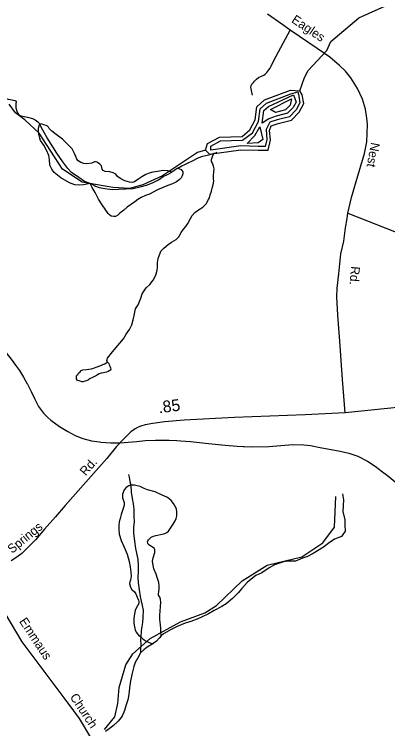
# Model space of a CAD drawing. Extents: x 2206922 to 2357709, y 510027 to 673830.
# Drawn here: x 2302635 to 2306591, y 537168 to 544730 of the extents above; entities that cross this region are included whole.
import ezdxf

# ---------------------------------------------------------------- set-up
doc = ezdxf.new("R2010")
doc.units = 0
for name, color, linetype in [('Exist Hydrographic Buffer Line', 7, 'Continuous'), ('Exist Hydrographic Creek Single Shore', 7, 'Continuous'), ('Exist Hydrographic Lake Shore', 7, 'Continuous'), ('Exist Hydrographic Misc Water Feature', 7, 'Continuous'), ('Exist Road Non-System Type 51', 7, 'Continuous'), ('Exist Road Secondary Mileage Hundredths English Label', 7, 'Continuous'), ('Exist Road Secondary Type 51 Attributed', 7, 'Continuous'), ('Exist Road Secondary Type 51 Label', 7, 'Continuous')]:
    doc.layers.add(name, color=color, linetype=linetype)

msp = doc.modelspace()

# ---------------------------------------------------------------- linework, layer by layer
at = {"layer": 'Exist Hydrographic Buffer Line'}
for points in [[(2305636.8, 543908.3), (2305647.3, 543862.6), (2305661.2, 543792.4), (2305621.8, 543719.4), (2305550.5, 543646.2), (2305420.5, 543613.7), (2305343, 543586.7), (2305301.5, 543511.9), (2305308.7, 543403.3), (2305292.9, 543331.4), (2305217.7, 543330.6), (2305034.6, 543336.3), (2304715.3, 543292.4), (2304715.9, 543333.3), (2304818.2, 543388.8), (2305050.8, 543398.2), (2305157, 543476.4), (2305223.4, 543595.6), (2305241.2, 543730), (2305307.5, 543790.2), (2305565.6, 543887.2), (2305636.8, 543908.3)], [(2305258.9, 543576.9), (2305279.4, 543710.6), (2305328.8, 543755.5), (2305591.1, 543878.9), (2305619.2, 543798.8), (2305589.2, 543743.3), (2305529.8, 543682.2), (2305410.6, 543652.5), (2305329.6, 543624.4), (2305258.9, 543576.9)], [(2305401.2, 543691.3), (2305349.9, 543720.7), (2305571.4, 543833.4), (2305556.4, 543767.2), (2305509, 543718.3), (2305401.2, 543691.3)], [(2305101.8, 543361.9), (2305182.8, 543445.8), (2305237.6, 543540), (2305268.3, 543405.6), (2305217.9, 543370.6), (2305101.8, 543361.9)]]:
    msp.add_lwpolyline(points, dxfattribs=at)
at = {"layer": 'Exist Hydrographic Creek Single Shore'}
for points in [[(2305660.2, 543918.8), (2305708.2, 544061.9), (2305749.2, 544135.7), (2305947.2, 544347.2), (2305987.2, 544440.7), (2306284.1, 544692.2), (2306591.3, 544829.3), (2306766.2, 544865.8), (2307040.2, 544860.5), (2307516.3, 544755), (2307941.2, 544752.4), (2308166.3, 544778)], [(2304659.3, 543291.1), (2304576.3, 543268.1), (2304204.3, 543020.1), (2303996.2, 542926.4), (2303855.1, 542884.6), (2303680.2, 542897.2), (2303355.2, 542953.1), (2303145.2, 543092.2), (2302900.2, 543472.9), (2302748.2, 543614.3), (2302647.1, 543685.8), (2302580.1, 543778.2)]]:
    msp.add_lwpolyline(points, dxfattribs=at)
at = {"layer": 'Exist Hydrographic Lake Shore'}
for points in [[(2304659.3, 543291.1), (2304683.3, 543361), (2304807.2, 543428.4), (2305049.1, 543438.1), (2305131.1, 543507.1), (2305188.1, 543614.3), (2305203.3, 543749.5), (2305286.2, 543825), (2305560.3, 543927.9), (2305660.2, 543918.8)], [(2305339.3, 543499.1), (2305356.3, 543548.9), (2305430.3, 543574.9), (2305571.2, 543610.1), (2305654.2, 543695.5), (2305703.2, 543786), (2305685.2, 543877.2), (2305660.2, 543918.8)], [(2304659.3, 543291.1), (2304701.1, 543250.1), (2305033.1, 543296.4), (2305217.3, 543290.6), (2305325.3, 543291.7), (2305349.3, 543401), (2305339.3, 543499.1)]]:
    msp.add_lwpolyline(points, dxfattribs=at)
at = {"layer": 'Exist Hydrographic Misc Water Feature'}
msp.add_line((2302772, 540819.9), (2302775.1, 540814.4), dxfattribs=at)
for points in [[(2302511.4, 543852.5), (2302531.9, 543844.9), (2302547.9, 543838.9), (2302571.7, 543831.2), (2302613.7, 543823.7), (2302641.6, 543817.9), (2302656, 543812.1), (2302656, 543804.4), (2302652.3, 543784.2), (2302652.5, 543760.3), (2302652.5, 543740.4), (2302660.9, 543704.3), (2302673.2, 543678.5), (2302685.5, 543662.4), (2302709.3, 543654.8), (2302739.4, 543649.1), (2302775.5, 543641.6), (2302827.6, 543628.1), (2302856.1, 543614.5), (2302884.4, 543590.7), (2302906.3, 543569.2)], [(2303439, 542939.1), (2303368.9, 542924.6), (2303325.2, 542920.1), (2303277.3, 542925.4), (2303220.9, 542946.8), (2303128.6, 542999.7), (2303057.9, 543054.9), (2303033.7, 543090.6), (2303010.7, 543134.6), (2303006.4, 543192.4), (2302999.6, 543236.4), (2302977.5, 543292.1), (2302948.8, 543343.8), (2302912.1, 543395.1), (2302903.9, 543419.1), (2302897.9, 543447.2), (2302893, 543484.8), (2302893, 543505.1), (2302893, 543522.9), (2302898.1, 543550.9), (2302906.3, 543569.2)], [(2304305, 543060.6), (2304263.1, 543072.1), (2304211.1, 543075.5), (2304151, 543066.8), (2304103, 543060.1), (2304065.3, 543050), (2304029.2, 543035.6), (2303985.5, 543010.9), (2303953.9, 542986.9), (2303908.4, 542956), (2303882.4, 542949.8), (2303854.7, 542951.6), (2303806.1, 542967), (2303762.2, 542986.6), (2303729.8, 543014.2), (2303709.7, 543036.3), (2303683.3, 543051.6), (2303645.5, 543061.3), (2303599.2, 543067.1), (2303585.2, 543072.8), (2303575.4, 543076.8), (2303565.4, 543090.4), (2303558.6, 543124.3), (2303542.4, 543144.2), (2303526.4, 543155.9), (2303510.4, 543164), (2303496.5, 543169.7), (2303484.2, 543167.5), (2303456.7, 543155), (2303404.6, 543148.7), (2303372.4, 543152.3), (2303338.4, 543159.8), (2303312.5, 543177.5), (2303298.4, 543197.5), (2303286.1, 543223.3), (2303271.7, 543257.1), (2303246.9, 543307), (2303200.6, 543350.1), (2303146.2, 543409.8), (2303063.6, 543466.9), (2303033.2, 543492.5), (2303004.7, 543522.3), (2302996.7, 543536.1), (2302988.3, 543545.9), (2302972.1, 543554), (2302948.4, 543561.6), (2302928.5, 543567.4), (2302906.3, 543569.2)], [(2303439, 542939.1), (2303380.4, 542960.5), (2303318.1, 543002), (2303241.4, 543056.9), (2303201.2, 543096.6), (2303148.3, 543169.8), (2303085.9, 543259.1), (2303043.1, 543328.8), (2302982, 543422), (2302953.1, 543477.8), (2302924.8, 543529.1), (2302906.3, 543569.2)], [(2303623.2, 541048.1), (2303616.8, 541066.1), (2303623, 541090.3), (2303634.7, 541106.4), (2303660.3, 541138.6), (2303693.9, 541179), (2303790.3, 541293.8), (2303819.6, 541344.2), (2303855.1, 541394.4), (2303878.9, 541444.7), (2303894.3, 541494.7), (2303905.7, 541542.9), (2303918.9, 541611), (2303948.4, 541653.2), (2303975.9, 541723.7), (2303989.4, 541769.9), (2304032.5, 541834), (2304070, 541870.5), (2304105.5, 541915), (2304135, 541967.4), (2304148.5, 542021.3), (2304152, 542051.6), (2304153.4, 542101.3), (2304159.2, 542143.4), (2304178.7, 542201.7), (2304188.3, 542221.7), (2304217.8, 542255.8), (2304263.4, 542292.3), (2304300.9, 542318.7), (2304350.7, 542347.3), (2304378.6, 542373.5), (2304402, 542419.9), (2304427.2, 542454.2), (2304453, 542484.4), (2304474.8, 542514.8), (2304500.4, 542566.8), (2304518, 542601.1), (2304547.6, 542633.1), (2304585.1, 542659.9), (2304633.3, 542688.4), (2304666.5, 542722.7), (2304693.8, 542768.9), (2304701.8, 542788.8), (2304711.4, 542818.9), (2304722.9, 542856.9), (2304734.4, 542903.1), (2304740.3, 542925.3), (2304747.9, 542963.5), (2304745.2, 542991.5), (2304745.4, 543025.1), (2304748.5, 543059.1), (2304750.8, 543095.3), (2304746.5, 543123), (2304736, 543155), (2304723.7, 543171.1), (2304723.7, 543193), (2304729.4, 543214.9), (2304739.1, 543236.9), (2304750.8, 543261.1)], [(2304366.5, 543101.2), (2304410.2, 543125.5), (2304441.7, 543141.8), (2304478, 543158.2), (2304523.6, 543178.9), (2304583, 543209.3), (2304632.9, 543229.8), (2304711, 543246.8), (2304750.8, 543261.1)], [(2304750.8, 543261.1), (2304768.4, 543265.3), (2304784.2, 543271.4)], [(2304366.5, 543101.2), (2304384.7, 543095.2), (2304400.9, 543085.5), (2304410.8, 543075.5), (2304421, 543063.8), (2304421.2, 543053.6), (2304421.2, 543041.8), (2304413.2, 543021.5), (2304402, 542999.3), (2304381.7, 542977.3), (2304351.9, 542955), (2304310.3, 542934.4), (2304262.5, 542918.1), (2304151, 542870.9), (2304067.9, 542826.2), (2304025.9, 542811.4), (2303980, 542791.2), (2303942.2, 542768.9), (2303912.7, 542746.6), (2303830.9, 542689.5), (2303793.6, 542657), (2303753.8, 542624.9), (2303732.3, 542604.6), (2303708.7, 542590.4), (2303684.3, 542590), (2303662.6, 542591.6), (2303642.3, 542607.6), (2303627.9, 542621.5), (2303565.4, 542712.5), (2303528.4, 542774), (2303491.9, 542843.6), (2303459.1, 542897.5), (2303439, 542939.1)], [(2304366.5, 543101.2), (2304338.4, 543082.7), (2304305, 543060.6)], [(2303439, 542939.1), (2303462.8, 542927.4), (2303495.2, 542911.6), (2303535, 542898.3), (2303593.4, 542884.6), (2303673.2, 542875.9), (2303739.2, 542878.5), (2303815.3, 542881.2), (2303895.1, 542886.3), (2303968.9, 542902.7), (2304036.6, 542921.7), (2304100.5, 542946.1), (2304163.9, 542978.8), (2304213.5, 543011.5), (2304259.3, 543035.8), (2304305, 543060.6)], [(2302314.1, 541436.1), (2302322.3, 541426.9), (2302393.3, 541341.4), (2302613.1, 541064.3), (2302649.4, 541017.1), (2302690.2, 540958.6)], [(2302314.1, 541436.1), (2302322.3, 541426.9), (2302393.3, 541341.4), (2302613.1, 541064.3), (2302649.4, 541017.1), (2302690.2, 540958.6)], [(2303623.2, 541048.1), (2303635.5, 541034.5), (2303641.6, 541020.6), (2303649.8, 540998.7), (2303653.7, 540986.7), (2303656.2, 540972.6), (2303653.9, 540964.8), (2303648.2, 540958.4), (2303628.1, 540950.4), (2303610.3, 540942.2), (2303592.6, 540938), (2303580.7, 540935.7), (2303556.5, 540931.6), (2303532.8, 540923.4), (2303516.6, 540913.3), (2303494.6, 540900.8), (2303485, 540897), (2303455, 540880.4), (2303439, 540874.3), (2303419.4, 540860.2), (2303401.3, 540852), (2303383.3, 540845.8), (2303363.6, 540841.5), (2303349.4, 540841.5), (2303333.4, 540845.2), (2303321.3, 540849), (2303305.4, 540855.1), (2303293.3, 540870.7), (2303293.5, 540884.8), (2303294.9, 540898.8), (2303298.6, 540908.8), (2303306.8, 540918.9), (2303316.4, 540930.9), (2303332.2, 540947.1), (2303344.1, 540959.1), (2303359.9, 540965.3), (2303400.1, 540971.8), (2303424.1, 540972.3), (2303452, 540976.6), (2303483.7, 540986.8), (2303503.8, 540995.1), (2303551.6, 541013.5), (2303573.1, 541023.6), (2303593.2, 541031.9), (2303609, 541040.1), (2303623.2, 541048.1)], [(2302690.2, 540958.6), (2302733.3, 540889.4), (2302772, 540819.9)], [(2302690.2, 540958.6), (2302733.3, 540889.4), (2302772, 540819.9)], [(2302775.1, 540814.4), (2302813.2, 540738.7), (2302851.2, 540657.2)], [(2302775.1, 540814.4), (2302813.2, 540738.7), (2302851.2, 540657.2)], [(2302851.2, 540657.2), (2302891.1, 540580.3), (2302944.5, 540506.7), (2302990.6, 540463.2)], [(2302851.2, 540657.2), (2302891.1, 540580.3), (2302944.5, 540506.7), (2302990.6, 540463.2)], [(2302990.6, 540463.2), (2303021.1, 540434.3), (2303115.3, 540366.4), (2303201.2, 540312.9), (2303279.5, 540273.2)], [(2302990.6, 540463.2), (2303021.1, 540434.3), (2303115.3, 540366.4), (2303201.2, 540312.9), (2303279.5, 540273.2)], [(2303279.5, 540273.2), (2303361.1, 540240.4), (2303451.1, 540217), (2303538.9, 540203.6)], [(2303279.5, 540273.2), (2303361.1, 540240.4), (2303451.1, 540217), (2303538.9, 540203.6)], [(2303756.3, 540194.4), (2303842.2, 540200.5), (2303934, 540209.7)], [(2303756.3, 540194.4), (2303842.2, 540200.5), (2303934, 540209.7)], [(2303934, 540209.7), (2304020.2, 540218.3), (2304132.3, 540222.5), (2304203.5, 540221.9)], [(2303934, 540209.7), (2304020.2, 540218.3), (2304132.3, 540222.5), (2304203.5, 540221.9)], [(2304203.5, 540221.9), (2304275.2, 540221.4), (2304356.9, 540218.2)], [(2304203.5, 540221.9), (2304275.2, 540221.4), (2304356.9, 540218.2)], [(2304356.9, 540218.2), (2304394, 540216.7), (2304502.4, 540208.9), (2304692.7, 540188.7)], [(2304356.9, 540218.2), (2304394, 540216.7), (2304502.4, 540208.9), (2304692.7, 540188.7)], [(2303538.9, 540203.6), (2303551.2, 540201.7), (2303656.2, 540194.4), (2303756.3, 540194.4)], [(2304692.7, 540188.7), (2304868.3, 540170.2), (2304997.2, 540158.6), (2305058.5, 540155.3)], [(2304692.7, 540188.7), (2304868.3, 540170.2), (2304997.2, 540158.6), (2305058.5, 540155.3)], [(2305058.5, 540155.3), (2305070.2, 540154.7), (2305162.3, 540152.2)], [(2305058.5, 540155.3), (2305070.2, 540154.7), (2305162.3, 540152.2)], [(2305162.3, 540152.2), (2305331.3, 540155.7), (2305585.3, 540176.2), (2305702.2, 540174), (2305771.3, 540165.2), (2305873.4, 540145.4)], [(2305162.3, 540152.2), (2305331.3, 540155.7), (2305585.3, 540176.2), (2305702.2, 540174), (2305771.3, 540165.2), (2305873.4, 540145.4)], [(2305873.4, 540145.4), (2306086.3, 540104.2), (2306179.6, 540083.4), (2306274.5, 540051.3), (2306375.2, 539999.9)], [(2305873.4, 540145.4), (2306086.3, 540104.2), (2306179.6, 540083.4), (2306274.5, 540051.3), (2306375.2, 539999.9)], [(2306375.2, 539999.9), (2306436.3, 539961.6), (2306472, 539935.6)], [(2306375.2, 539999.9), (2306436.3, 539961.6), (2306472, 539935.6)], [(2306472, 539935.6), (2306488.4, 539923.8), (2306535.3, 539888.7), (2306587.2, 539846.6)], [(2306472, 539935.6), (2306488.4, 539923.8), (2306535.3, 539888.7), (2306587.2, 539846.6)], [(2303845.9, 539857.3), (2303852.2, 539831.3), (2303860.6, 539785.5), (2303869, 539745.6)], [(2306587.2, 539846.6), (2306825.3, 539653.9), (2306889.3, 539605.1), (2306954.3, 539561.6), (2307014.3, 539529.6)], [(2306587.2, 539846.6), (2306825.3, 539653.9), (2306889.3, 539605.1), (2306954.3, 539561.6), (2307014.3, 539529.6)], [(2303869, 539745.6), (2303849.1, 539737.4), (2303821.5, 539721.1), (2303799.7, 539694.9), (2303782.3, 539650.7), (2303782.5, 539610.7), (2303797.1, 539562.9), (2303797.5, 539535), (2303787.6, 539500.8), (2303768.6, 539434.7), (2303756.9, 539394.6), (2303747.2, 539356.5), (2303741.7, 539316.5), (2303742.3, 539280.5), (2303746.6, 539228.6), (2303767.5, 539160.8), (2303800.1, 539089.2), (2303829.1, 539015.6), (2303851.8, 538937.9), (2303862.5, 538882.1), (2303870.9, 538824.2), (2303871.5, 538784.1), (2303866, 538742.2), (2303860.2, 538722.1), (2303856.3, 538704.1), (2303864.7, 538666.1), (2303880.9, 538642.3), (2303907.2, 538616.7), (2303921.5, 538594.8), (2303937.7, 538561), (2303952.3, 538527.2), (2303954.1, 538513.2), (2303952.5, 538495.2), (2303938.8, 538467.1), (2303927.1, 538445), (2303915.2, 538418.8), (2303907.8, 538382.8), (2303902.3, 538334.8), (2303900.8, 538286.8), (2303909.2, 538244.9), (2303915.4, 538215), (2303927.7, 538189.1), (2303952.3, 538159.4), (2303974.2, 538141.7)], [(2304189.9, 538152), (2304187.7, 538191.9), (2304187.3, 538229.9), (2304184.8, 538267.8), (2304176.2, 538323.7), (2304175.8, 538365.7), (2304181.3, 538415.7), (2304184.8, 538457.7), (2304188.3, 538509.8), (2304184, 538531.7), (2304179.7, 538555.7), (2304169.4, 538571.5), (2304163.5, 538583.4), (2304163.3, 538597.4), (2304167, 538615.5), (2304170.7, 538649.5), (2304170.5, 538681.5), (2304166, 538715.4), (2304153.4, 538757.2), (2304138.9, 538805), (2304114.5, 538860.8), (2304106.1, 538898.7), (2304102, 538918.6), (2304099.5, 538942.5), (2304101.6, 538960.5), (2304107.3, 538978.6), (2304122.5, 539034.7), (2304124.5, 539048.8), (2304124.3, 539062.7), (2304120.2, 539072.7), (2304116.1, 539078.6), (2304069.8, 539108.2), (2304059.7, 539114), (2304053.8, 539122), (2304049.5, 539133.9), (2304047.4, 539145.9), (2304051.1, 539155.9), (2304057.3, 539165.9), (2304069, 539182.1), (2304085, 539194.2), (2304108.7, 539206.5), (2304132.7, 539214.7), (2304202.5, 539227.5), (2304228.5, 539235.8), (2304252.3, 539246), (2304268.1, 539260.2), (2304283.7, 539280.4), (2304319.1, 539332.7), (2304339, 539368.9), (2304348.5, 539393), (2304358.3, 539423), (2304357.7, 539463), (2304351.5, 539497), (2304337.2, 539526.8), (2304321, 539552.6), (2304296.6, 539582.3), (2304270.3, 539606), (2304250.2, 539617.8), (2304202, 539641.2), (2304127.8, 539674.4), (2304047.4, 539697.5), (2304011.6, 539709.2), (2303967.3, 539730.7), (2303936.9, 539740.3), (2303909, 539746), (2303888.9, 539745.8), (2303869, 539745.6)], [(2303869, 539745.6), (2303874, 539671.7), (2303884.4, 539605.8), (2303893.2, 539550), (2303899.8, 539492.1), (2303902.7, 539412.2), (2303903.3, 539362.2), (2303898, 539296.2), (2303898.6, 539240.2), (2303907.4, 539154.4), (2303918.3, 539076.5), (2303928.7, 539026.7), (2303943.5, 538958.8), (2303946.1, 538892.9), (2303947, 538830.9), (2303943.5, 538769), (2303946.1, 538715), (2303957, 538639.2), (2303967.7, 538567.3), (2303980.2, 538519.5), (2303990.6, 538473.6), (2303999.2, 538421.8), (2303998.2, 538343.8), (2303992.7, 538291.8), (2303987.1, 538249.7), (2303977.7, 538203.6), (2303974.2, 538141.7)], [(2303592.2, 537160.9), (2303699.3, 537293.3), (2303731.2, 537435.6), (2303746.2, 537603.6), (2303818.2, 537846.1), (2303892.2, 537960.6), (2304073.3, 538122.1), (2304396.2, 538299.2), (2304653.2, 538394.9), (2304777.2, 538472.1), (2305049.3, 538732.5), (2305314.2, 538900.7), (2305680.3, 538987.6), (2305903.4, 539134.4), (2306026.2, 539300.2), (2306039.3, 539625.5)], [(2306112.7, 539653.9), (2306121.5, 539592), (2306116.8, 539466), (2306135.7, 539378.3), (2306136.3, 539324.3), (2306141, 539260.4), (2306101.9, 539202), (2306026, 539173.2), (2305992.4, 539148.8), (2305974.5, 539140.7), (2305910.9, 539090), (2305799.8, 539022.8), (2305742.2, 538992.2), (2305688.3, 538973.7), (2305612.8, 538942.9), (2305532.8, 538940), (2305485.1, 538935.5), (2305391.3, 538904.5), (2305335.8, 538871.9), (2305256.2, 538819.1), (2305194.7, 538788.4), (2305145.1, 538751.9), (2305103.5, 538717.5), (2305044.2, 538650.9), (2305006.7, 538606.5), (2304945.6, 538547.9), (2304879.9, 538491.2), (2304832.2, 538462.7), (2304751, 538417.8), (2304693.1, 538385.3), (2304617.7, 538350.5), (2304577.9, 538332), (2304506.3, 538301.3), (2304444.4, 538284.6), (2304358.9, 538251.7), (2304297.2, 538217.1), (2304245.7, 538190.5), (2304215.8, 538172.2), (2304189.9, 538152)], [(2303974.2, 538141.7), (2303972.8, 538113.6), (2303975.3, 538055.7), (2303971.8, 538005.7), (2303972.2, 537969.7)], [(2303974.2, 538141.7), (2303994.5, 538123.9), (2304010.7, 538108.1), (2304030.8, 538094.2), (2304055, 538082.6), (2304081.1, 538074.8), (2304106.9, 538069.1)], [(2304189.9, 538152), (2304170.5, 538125.8), (2304140.7, 538093.5), (2304106.9, 538069.1)], [(2304106.9, 538069.1), (2304103, 538065.1), (2304043.5, 538030.5), (2304005.8, 538002.1), (2303972.2, 537969.7)], [(2303972.2, 537969.7), (2303942.7, 537917.4), (2303915.2, 537869.1), (2303899.8, 537827), (2303882.6, 537756.9), (2303867.4, 537674.8), (2303854.3, 537602.6), (2303850.8, 537562.6), (2303845.3, 537508.6), (2303837.5, 537474.6), (2303818.2, 537410.4), (2303802.8, 537360.3), (2303777.6, 537302), (2303736, 537249.6), (2303684.7, 537201.1), (2303655, 537176.7), (2303601.2, 537140.2)]]:
    msp.add_lwpolyline(points, dxfattribs=at)
at = {"layer": 'Exist Road Non-System Type 51'}
for points in [[(2305159.5, 543873.4), (2305151.1, 543907.2), (2305144.8, 543941), (2305140.7, 543957), (2305144.5, 543973), (2305152.2, 543989.1), (2305170, 544009.4), (2305179.9, 544021.4), (2305201.6, 544043.7), (2305221.6, 544059.9), (2305253.4, 544074.2), (2305277.1, 544086.3), (2305291.1, 544096.5), (2305310.9, 544112.7), (2305330.6, 544140.9), (2305344.4, 544159.1), (2305354.2, 544179.3), (2305385.5, 544241.5), (2305557.1, 544562.9)], [(2306168.8, 542625.1), (2306780.6, 542385.4), (2306896.3, 542339.6), (2307091.5, 542272.3)]]:
    msp.add_lwpolyline(points, dxfattribs=at)
at = {"layer": 'Exist Road Secondary Type 51 Attributed'}
for points in [[(2306138.6, 540510.9), (2306113, 540865), (2306084.1, 541269), (2306062.5, 541546.4), (2306053.1, 541737.7), (2306056.5, 541831.9), (2306074, 541982.7), (2306094.8, 542192.8), (2306125.8, 542330.2), (2306144.6, 542470.2), (2306160.8, 542567.2), (2306168.8, 542625.1), (2306208.6, 542790.7), (2306257.7, 542960.4), (2306345.8, 543256.7), (2306370.7, 543380.6), (2306377.5, 543563.7), (2306369.4, 543631), (2306354.6, 543724), (2306322.3, 543830.3), (2306271.1, 543944.8), (2306198.5, 544057.9), (2306143.3, 544129.3), (2306078.7, 544188.6), (2305976.4, 544276.1), (2305844.5, 544369), (2305557.1, 544562.9), (2305469.6, 544626.2), (2305316.9, 544731.3)], [(2309785.3, 540257), (2309588.4, 540254.8), (2309358.6, 540248.4), (2309002.8, 540240.6), (2308806.8, 540238.5), (2308708.9, 540241.4), (2308658.8, 540247), (2308606.6, 540262.3), (2308566.5, 540279.9), (2308516.2, 540311.2), (2308439.7, 540362.6), (2308371, 540425.6), (2308312.3, 540491.1), (2308253.8, 540538.3), (2308225.7, 540556), (2308189.7, 540565.7), (2308137.5, 540575), (2308067.5, 540588.4), (2307977.4, 540595.4), (2307871.4, 540596.3), (2307625.7, 540591.6), (2306724.4, 540569.9), (2306138.6, 540510.9)], [(2306138.6, 540510.9), (2305716.6, 540490.7), (2304969, 540462.4), (2304434.6, 540434.1), (2304226, 540416.6), (2304103.6, 540397.7), (2304021.5, 540384.3), (2303977, 540370.8), (2303947.4, 540361.4), (2303916.5, 540342.5), (2303869.4, 540308.9), (2303802.1, 540242.9), (2303718.6, 540155.3), (2303613.8, 540028.7), (2303528.8, 539933.9), (2303174.2, 539530.5), (2303070.6, 539412), (2302956.2, 539281.4), (2302859.3, 539166.9), (2302713.2, 539021.5), (2302662.1, 538983.8), (2302601.5, 538946.1)], [(2302271.8, 538824.9), (2302715.9, 538086.7), (2303203.5, 537439.3), (2303321.6, 537274.7), (2303452.8, 537058.6), (2303535.6, 536903), (2303632.5, 536735.4), (2303674.9, 536668.7), (2303723.4, 536616.2), (2303763.7, 536585.9), (2303845.1, 536543.9), (2303944, 536511.5), (2304092.8, 536478.8), (2304564.8, 536403.5), (2304708.2, 536387.3), (2304896.9, 536380.2), (2304708.2, 536387.3), (2304896.9, 536380.2), (2305567.2, 536374.2), (2305913.4, 536353), (2306091.1, 536302.5), (2306337.4, 536209.6), (2306828, 536001.5)]]:
    msp.add_lwpolyline(points, dxfattribs=at)

# ---------------------------------------------------------------- texts
at = {"layer": 'Exist Road Secondary Mileage Hundredths English Label'}
msp.add_text('.85', height=125, rotation=7.20698, dxfattribs=at).set_placement((2304168.3, 540506.4))
at = {"layer": 'Exist Road Secondary Type 51 Label'}
for s, rotation, p in [('Eagles', 326.13159, (2305563.5, 544650.8)), ('Nest', 259.48634, (2306414.8, 543378.4)), ('Rd.', 265.3006, (2306202.4, 542066.1)), ('Rd.', 48.72794, (2303390.5, 539838.8)), ('Springs', 39.1455, (2302610.8, 539018.1)), ('Emmaus', 303.62814, (2302682.7, 538304.1)), ('Church', 303.62814, (2303219.7, 537503.7))]:
    msp.add_text(s, height=95, rotation=rotation, dxfattribs=at).set_placement(p)

doc.saveas('drawing.dxf')
